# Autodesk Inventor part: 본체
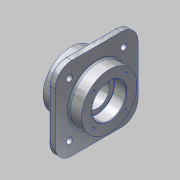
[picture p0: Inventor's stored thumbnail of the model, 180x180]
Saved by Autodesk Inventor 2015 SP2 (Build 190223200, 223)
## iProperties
Created: 2015-07
Part Number: 본체
Material: 알루미늄 6061
Document SubType Name: Modeling
Designer: AMC
Density: 2.7 g/cm^3
Appearance: 알루미늄 - 평지
Author: AMC
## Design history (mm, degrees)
sketch "스케치1"
  geometry: L1 (75, -75)-(-75, -75); L2 (-75, -75)-(-75, 75); L3 (-75, 75)-(75, 75); L4 (75, 75)-(75, -75); L5 (75, -75)-(-75, 75); L6 (-75, -75)-(75, 75); 1 further point
  constraints: 12 end point, 2 midpoint, 2 parallel, 1 horizontal, 1 perpendicular
  dimensions: "d0" = 150 distance of L2.end L3.end; "d1" = 150 distance of L1.end L2.end
extrude "돌출1" new body sketch "스케치1" stored distance "d2" = 12; taper "d3" = 0 deg
fillet "모깎기1" dims "d4" = 30
sketch "스케치2"
  geometry: L1 (45, 75)-(-45, 75) reference; L2 (75, -45)-(75, 45) reference; L3 (-75, 45)-(-75, -45) reference; C1 r 10 at (49, 49); C2 r 10 at (49, -49); C3 r 10 at (-49, -49); C4 r 10 at (-49, 49); 1 further point
  constraints: 4 centre point, 2 horizontal alignment, 1 vertical alignment
  dimensions: "d5" = 20 diameter of C1; "d6" = 20 diameter of C2; "d7" = 20 diameter of C3; "d8" = 20 diameter of C4; "d9" = 98 distance of C2.centre C1.centre; "d10" = 98 distance of C3.centre C2.centre; "d11" = 26 distance from line of L1 C1.centre; "d12" = 26 distance from line of L2 C1.centre; "d13" = 26 distance from line of L3 C4.centre
extrude "돌출2" join sketch "스케치2" distance "d14" = 5; taper "d15" = 0 deg
sketch "스케치3"
  geometry: C1 r 50 at (0, 0); 1 further point
  constraints: 1 centre point, 1 coincident
  dimensions: "d16" = 100 diameter of C1
extrude "돌출3" join sketch "스케치3" distance "d17" = 29; taper "d19" = 0 deg; dims "d18" = 41, "d20" = 0
hole "구멍1" diameter "d23" = 11; stored, may be unused: countersink angle "d27" = 90 deg, drill point angle "d29" = 118 deg; dims "d21" = 10, "d22" = 10, "d24" = 6, "d25" = 4, "d26" = 2, "d28" = 8
hole "구멍2" diameter "d32" = 11; stored, may be unused: countersink angle "d36" = 90 deg, drill point angle "d38" = 118 deg; dims "d30" = 10, "d31" = 10, "d33" = 6, "d34" = 4, "d35" = 2, "d37" = 8
hole "구멍3" diameter "d41" = 11; stored, may be unused: countersink angle "d45" = 90 deg, drill point angle "d47" = 118 deg; dims "d39" = 10, "d40" = 10, "d42" = 6, "d43" = 4, "d44" = 2, "d46" = 8
hole "구멍4" diameter "d50" = 11; stored, may be unused: countersink angle "d54" = 90 deg, drill point angle "d56" = 118 deg; dims "d48" = 10, "d49" = 10, "d51" = 6, "d52" = 4, "d53" = 2, "d55" = 8
hole "구멍5" diameter "d59" = 45; stored, may be unused: countersink angle "d63" = 90 deg, drill point angle "d65" = 118 deg; dims "d57" = 10, "d58" = 10, "d60" = 6, "d61" = 62, "d62" = 22, "d64" = 8
hole "구멍6" diameter "d68" = 62; stored, may be unused: countersink angle "d72" = 90 deg, drill point angle "d74" = 0 deg; dims "d66" = 10, "d67" = 10, "d69" = 6, "d70" = 62, "d71" = 22, "d73" = 22
sketch "스케치4"
  geometry: 2 further points
  constraints: 1 horizontal alignment, 1 other
  dimensions: "d75" = 65 distance of point (0, 0) point (65, 0)
feature "엠보싱1" sketch "스케치4" dims "d0" = 150, "d1" = 150, "d76" = 1, "d77" = 0
sketch "스케치5"
  geometry: L1 (0, 0)-(0, -41); L2 (0, 0)-(28.991, -28.991); A1 r 41 centre (0, 0) between (0, -41) and (28.991, -28.991); 2 further points
  constraints: 4 end point, 2 coincident, 2 point on circle, 1 centre point, 1 vertical
  dimensions: "d78" = 82 diameter of A1; "d79" = 45 deg angle of L1 L2
hole "구멍7" sketch "스케치5" at (28.991, -28.991) diameter "d80" = 4.917; stored, may be unused: countersink angle "d84" = 90 deg, drill point angle "d86" = 118 deg; dims "d81" = 10, "d82" = 62, "d83" = 22, "d85" = 13
sketch "스케치6"
  geometry: L1 (0, 0)-(0, 41); L2 (0, 0)-(-28.991, 28.991); A1 r 41 centre (0, 0) between (0, 41) and (-28.991, 28.991); 2 further points
  constraints: 4 end point, 2 coincident, 2 point on circle, 1 centre point, 1 vertical
  dimensions: "d90" = 82 diameter of A1; "d91" = 45 deg angle of L1 L2
hole "구멍8" sketch "스케치6" at (-28.991, 28.991) diameter "d92" = 4.917; stored, may be unused: countersink angle "d96" = 90 deg, drill point angle "d98" = 118 deg; dims "d93" = 10, "d94" = 62, "d95" = 22, "d97" = 13
fillet "모깎기2" dims "d102" = 3
fillet "모깎기3" dims "d103" = 3
chamfer "모따기1" distance "d104" = 1; stored, may be unused: second distance "d105" = 2, angle "d106" = 45 deg
fillet "모깎기4" dims "d107" = 0.3
node "솔리드1"
pattern_circular "원형 패턴1" dims angle "d88" = 360 deg
pattern_circular "원형 패턴2" dims angle "d100" = 360 deg
